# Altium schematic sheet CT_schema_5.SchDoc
size 373 x 245 mm
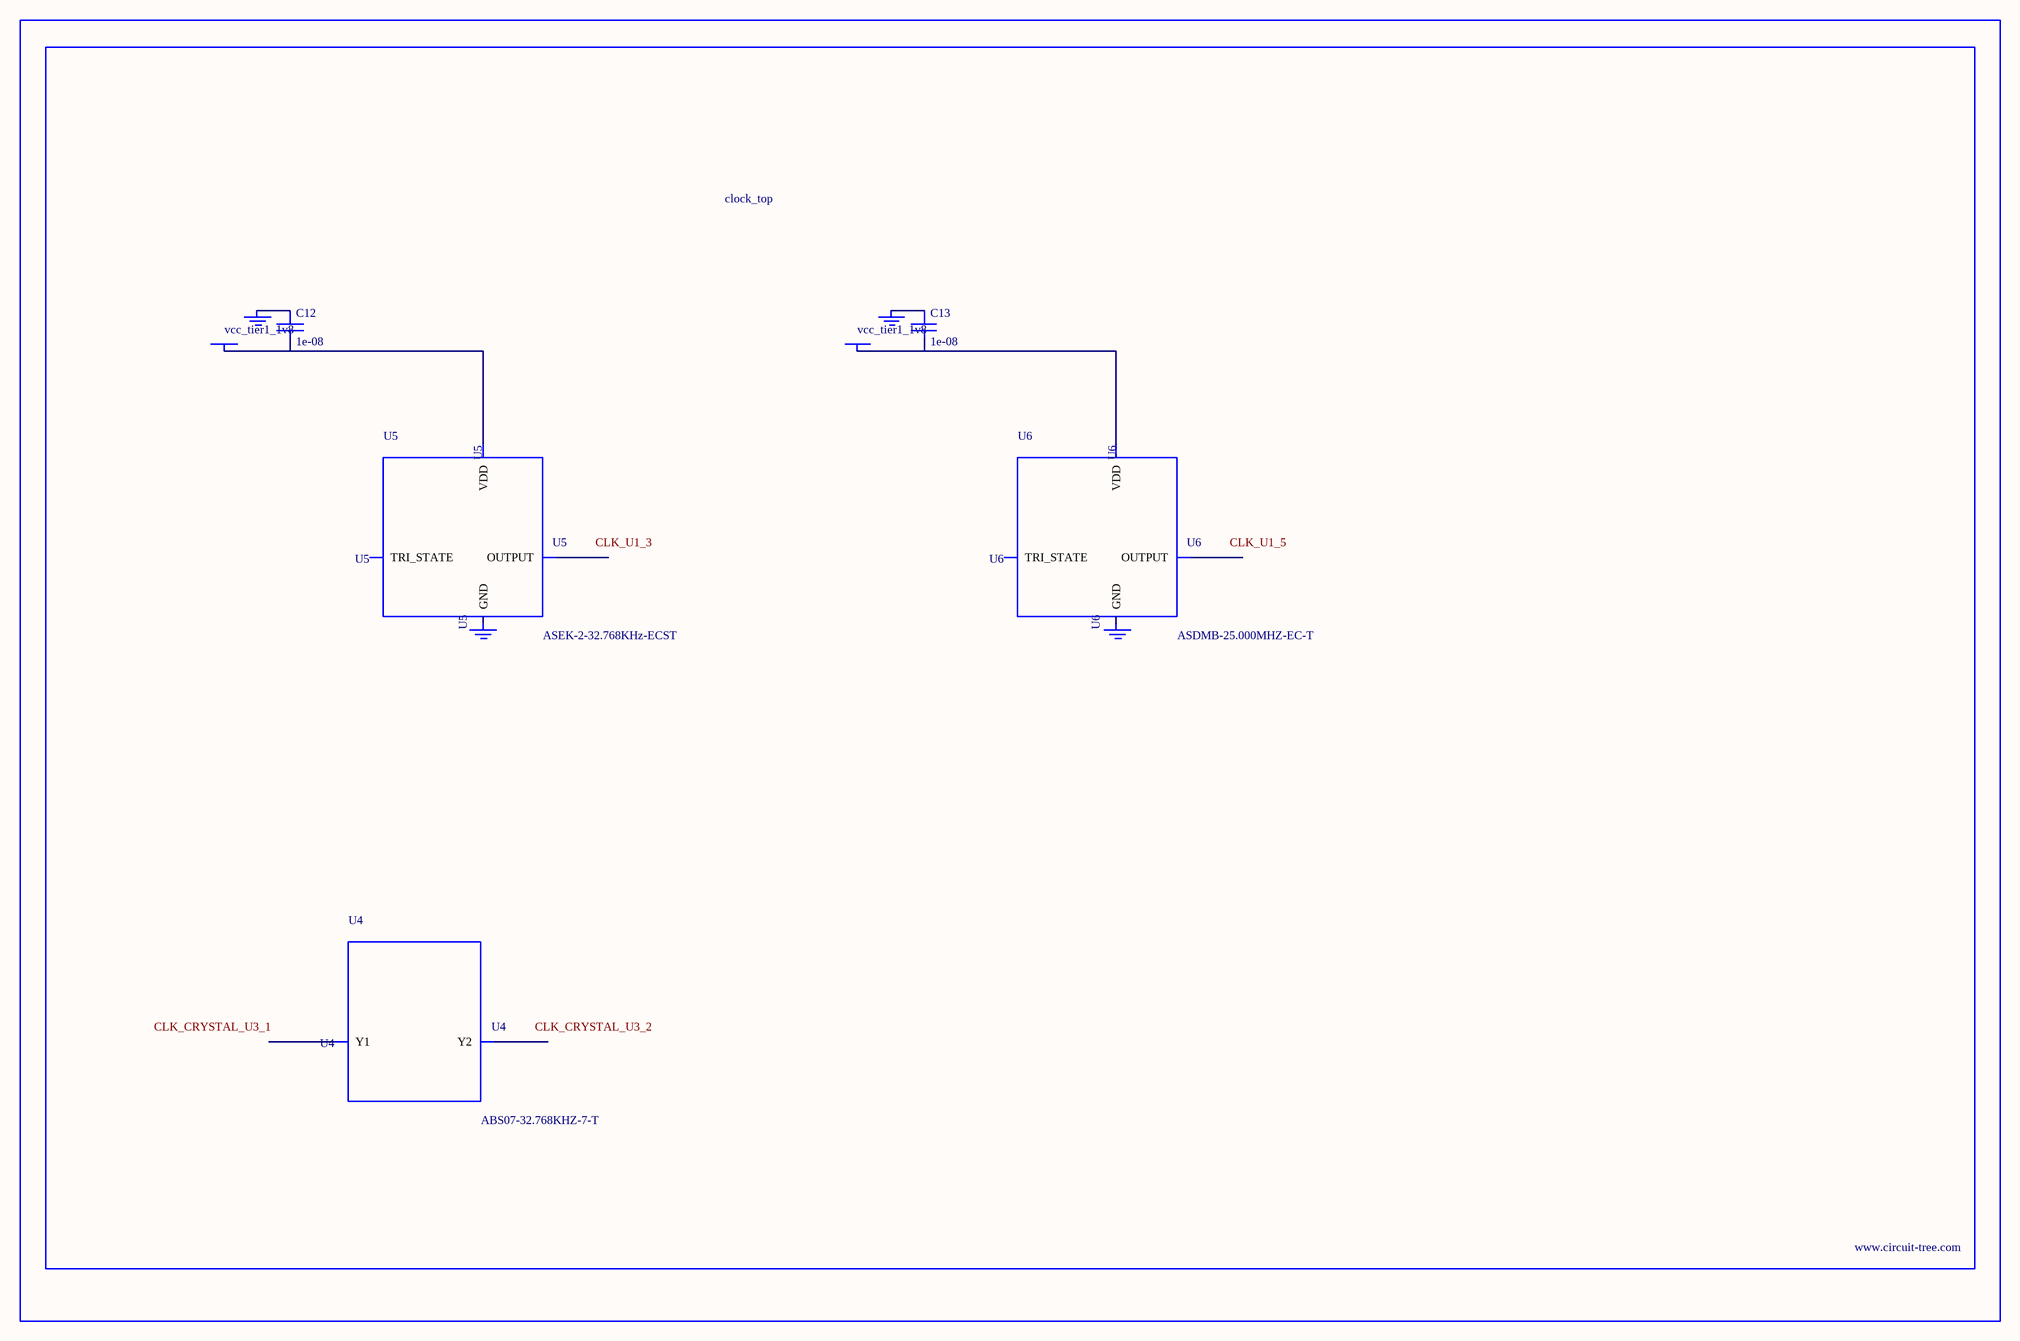
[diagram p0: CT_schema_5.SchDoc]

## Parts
BORDER4  (no value)
C12  1e-08  [C0402]
C13  1e-08  [C0402]
GND_INSTANCE_4_0  (no value)
GND_INSTANCE_4_1  (no value)
GND_INSTANCE_4_2  (no value)
GND_INSTANCE_4_3  (no value)
POWER_INSTANCE_4_0  vcc_tier1_1v8
POWER_INSTANCE_4_1  vcc_tier1_1v8
U4  ABS07-32.768KHZ-7-T  [ABS07-32.768KHZ-7-T]
U5  ASEK-2-32.768KHz-ECST  [ASEK]
U6  ASDMB-25.000MHZ-EC-T  [ASDMB-XX.XXXXMHZ-XX-XX-XXX]

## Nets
NetC12_1: C12.1 GND_INSTANCE_4_0.0(GND)
NetC12_2: C12.2 POWER_INSTANCE_4_0.0(PWR) U5.4(VDD)
NetC13_1: C13.1 GND_INSTANCE_4_2.0(GND)
NetC13_2: C13.2 POWER_INSTANCE_4_1.0(PWR) U6.4(VDD)

Not connected (* = marked no-connect by the designer): GND_INSTANCE_4_1 0(GND); GND_INSTANCE_4_3 0(GND); U4 1(Y1) 2(Y2); U5 1(TRI_STATE) 2(GND) 3(OUTPUT); U6 1(TRI_STATE) 2(GND) 3(OUTPUT)

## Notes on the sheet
- Labels drawn without touching a wire or pin: CLK_CRYSTAL_U3_1, CLK_CRYSTAL_U3_2, CLK_U1_3, CLK_U1_5

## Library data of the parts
BORDER4 = BORDER_PAGE4
C12 C13 = C0402C103K3RAC
GND_INSTANCE_4_0-GND_INSTANCE_4_3 = GND
POWER_INSTANCE_4_0 POWER_INSTANCE_4_1 = PWR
